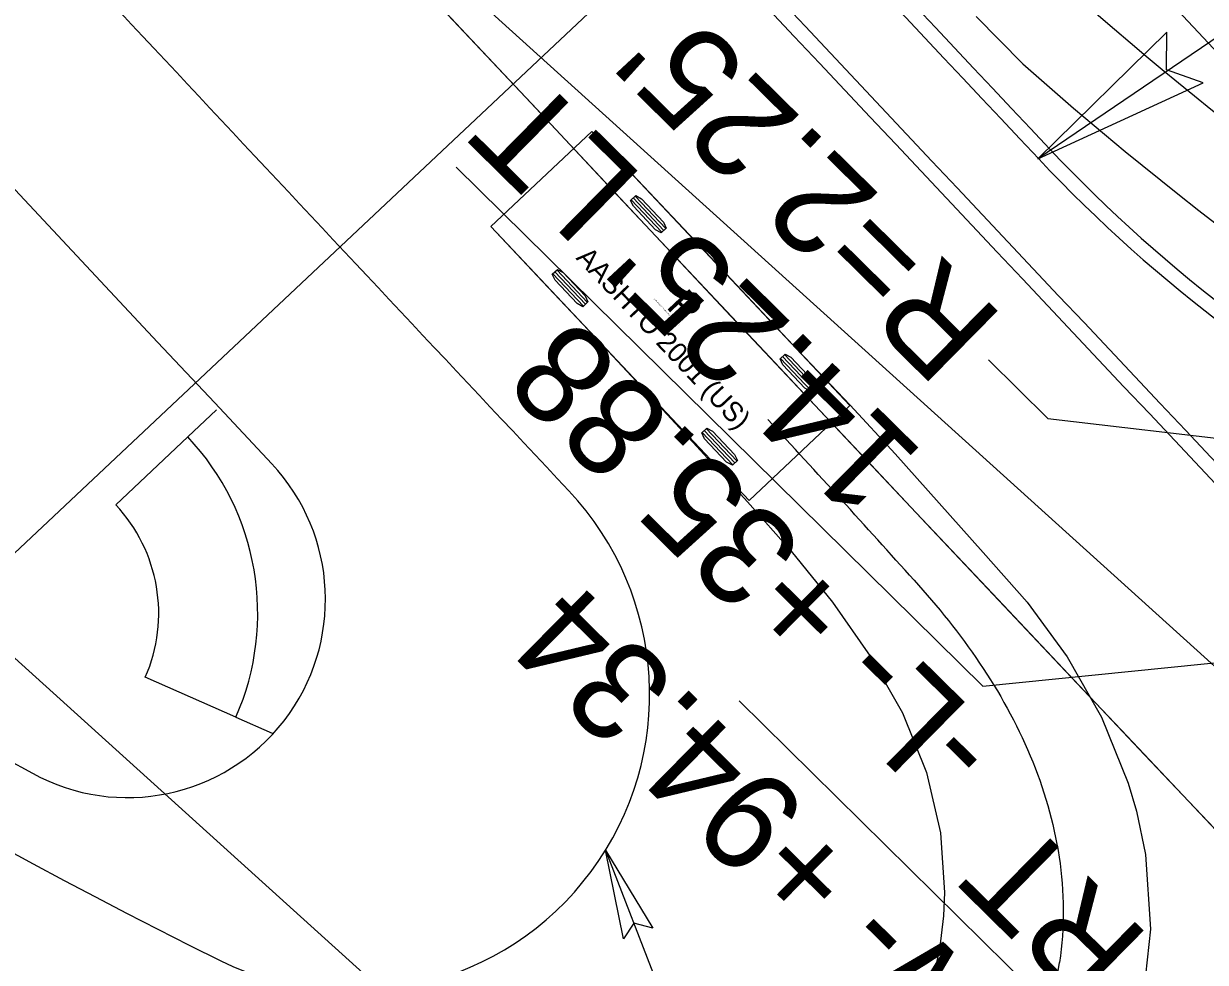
# Model space of a CAD drawing. Extents: x 1262642 to 1268358, y 767825 to 773481.
# Drawn here: x 1266689.1 to 1266748.8, y 772158.3 to 772205.7 of the extents above; entities that cross this region are included whole.
import ezdxf

# ---------------------------------------------------------------- set-up
doc = ezdxf.new("R2010")
doc.units = 0
for name, color, linetype in [('Prop Conc 2ft 6in Curb and Gutter', 7, 'Continuous'), ('Prop Conc 4in Sidewalk', 7, 'Continuous'), ('Prop Conc 5in Monolithic Keyed In Island', 7, 'Continuous'), ('Prop Dimension', 7, 'Continuous'), ('Prop Dimension Text', 7, 'Continuous'), ('Prop EOT', 7, 'Continuous'), ('Prop Horizontal Alignment', 7, 'Continuous'), ('Prop Horizontal Alignment Station Label', 7, 'Continuous'), ('Prop Lane Lines', 7, 'Continuous'), ('Prop Paved Shoulder', 7, 'Continuous'), ('Prop Shade Light', 7, 'Continuous'), ('Prop Shade Medium', 7, 'Continuous'), ('Prop Terminator CELL', 7, 'Continuous'), ('Scratch_Level_3', 7, 'Continuous')]:
    doc.layers.add(name, color=color, linetype=linetype)

msp = doc.modelspace()

# ---------------------------------------------------------------- linework, layer by layer
at = {"layer": 'Prop Conc 2ft 6in Curb and Gutter'}
for p, q in [((1266697.439, 772184.846), (1266698.896, 772186.216)), ((1266699.869, 772170.703), (1266701.7, 772169.897))]:
    msp.add_line(p, q, dxfattribs=at)
msp.add_arc((1266687.97, 772175.939), 13, 336.24997, 43.24771, dxfattribs=at)
at = {"layer": 'Prop Conc 4in Sidewalk'}
for p, q in [((1266693.797, 772181.42), (1266697.439, 772184.846)), ((1266699.869, 772170.703), (1266695.293, 772172.717))]:
    msp.add_line(p, q, dxfattribs=at)
msp.add_arc((1266687.97, 772175.939), 8, 336.24997, 43.24771, dxfattribs=at)
at = {"layer": 'Prop Conc 5in Monolithic Keyed In Island'}
for centre, radius, start, end in [((1275047.307, 780021.225), 11410.25, 222.8296601, 223.2792706), ((1275047.307, 780021.225), 11414.25, 222.8297896, 223.4298287), ((1266795.008, 772250.288), 75, 223.27927, 262.87792)]:
    msp.add_arc(centre, radius, start, end, dxfattribs=at)
at = {"layer": 'Prop Dimension'}
for p, q in [((1266731.744, 772134.821), (1266682.387, 772179.383)), ((1266718.539, 772163.987), (1266721.575, 772156.135))]:
    msp.add_line(p, q, dxfattribs=at)
at = {"layer": 'Prop Dimension Text'}
for p, q in [((1266710.996, 772198.463), (1266737.577, 772172.272)), ((1266737.867, 772188.735), (1266740.875, 772185.77)), ((1266751.861, 772145.344), (1266725.28, 772171.535))]:
    msp.add_line(p, q, dxfattribs=at)
for points in [[(1266754.434, 772208.43), (1266740.368, 772198.877)], [(1266740.875, 772185.77), (1266761.026, 772183.425)], [(1266737.577, 772172.272), (1266758.096, 772174.335)]]:
    msp.add_lwpolyline(points, dxfattribs=at)
at = {"layer": 'Prop EOT'}
for centre, radius, start, end in [((1275047.307, 780021.225), 11409.5, 222.8296601, 223.2792706), ((1275047.307, 780021.225), 11415, 222.8297896, 223.4298287), ((1266840.27, 772443.458), 318.091, 223.23333, 243.65317), ((1275047.307, 780021.225), 11439, 222.9935866, 223.2588472), ((1266795.008, 772250.288), 74.25, 223.27927, 262.87792), ((1266705.758, 772171.851), 15, 243.65317, 43.25885)]:
    msp.add_arc(centre, radius, start, end, dxfattribs=at)
at = {"layer": 'Prop Horizontal Alignment'}
msp.add_arc((1275047.307, 780021.225), 11400, 222.9935866, 225.4043192, dxfattribs=at)
at = {"layer": 'Prop Horizontal Alignment Station Label'}
for p, q in [((1266683.114, 772173.743), (1266860.999, 772340.982)), ((1266769.823, 772154.715), (1266566.881, 772338.064))]:
    msp.add_line(p, q, dxfattribs=at)
at = {"layer": 'Prop Lane Lines'}
for start, end in [(216.3674993, 223.5476842), (222.9935866, 225.3637298)]:
    msp.add_arc((1275047.307, 780021.225), 11427, start, end, dxfattribs=at)
at = {"layer": 'Prop Paved Shoulder'}
for centre, radius, start, end in [((1275047.307, 780021.225), 11449, 220.5050908, 223.2024475), ((1266840.27, 772443.458), 314.091, 223.23333, 241.33253), ((1266694.39, 772176.643), 10, 241.33253, 43.20245)]:
    msp.add_arc(centre, radius, start, end, dxfattribs=at)
at = {"layer": 'Prop Shade Light'}
for centre, radius, start, end in [((1275047.307, 780021.225), 11449, 220.5050908, 223.2024475), ((1266840.27, 772443.458), 314.091, 223.23333, 241.33253), ((1266840.27, 772443.458), 318.091, 223.23333, 243.65317), ((1275047.307, 780021.225), 11439, 222.9935866, 223.2588472), ((1266694.39, 772176.643), 10, 241.33253, 43.20245), ((1266705.758, 772171.851), 15, 243.65317, 43.25885)]:
    msp.add_arc(centre, radius, start, end, dxfattribs=at)
at = {"layer": 'Prop Shade Medium'}
for centre, radius, start, end in [((1275047.307, 780021.225), 11410.25, 222.8296601, 223.2792706), ((1275047.307, 780021.225), 11414.25, 222.8297896, 223.4298287), ((1266795.008, 772250.288), 75, 223.27927, 262.87792)]:
    msp.add_arc(centre, radius, start, end, dxfattribs=at)
at = {"layer": 'Prop Terminator CELL'}
for points in [[(1266746.884, 772205.276), (1266740.368, 772198.877), (1266748.719, 772202.715), (1266746.862, 772203.375)], [(1266719.439, 772159.51), (1266718.539, 772163.987), (1266720.917, 772160.055), (1266719.963, 772160.303)]]:
    msp.add_lwpolyline(points, close=True, dxfattribs=at)
at = {"layer": 'Scratch_Level_3'}
for p, q in [((1266717.837, 772200.259), (1266712.745, 772195.456)), ((1266730.874, 772186.437), (1266717.837, 772200.259)), ((1266721.369, 772195.171), (1266719.826, 772196.808)), ((1266721.472, 772195.267), (1266719.928, 772196.904)), ((1266721.574, 772195.364), (1266720.03, 772197)), ((1266712.745, 772195.456), (1266725.782, 772181.634)), ((1266717.414, 772191.44), (1266715.87, 772193.077)), ((1266717.516, 772191.536), (1266715.972, 772193.173)), ((1266717.618, 772191.633), (1266716.075, 772193.27)), ((1266728.917, 772187.169), (1266727.373, 772188.805)), ((1266729.019, 772187.265), (1266727.476, 772188.902)), ((1266729.122, 772187.362), (1266727.578, 772188.998)), ((1266725.782, 772181.634), (1266730.874, 772186.437)), ((1266730.874, 772186.437), (1266730.874, 772186.437)), ((1266725.166, 772183.631), (1266723.622, 772185.267)), ((1266724.961, 772183.438), (1266723.418, 772185.074)), ((1266725.064, 772183.534), (1266723.52, 772185.171))]:
    msp.add_line(p, q, dxfattribs=at)
for points in [[(1266737.254, 772206.068), (1266739.603, 772203.675), (1266742.157, 772201.436), (1266744.774, 772199.257), (1266747.424, 772197.118), (1266748.494, 772196.274)], [(1266717.837, 772200.259), (1266720.452, 772197.502), (1266723.058, 772194.736), (1266725.66, 772191.966), (1266728.267, 772189.202), (1266730.885, 772186.446), (1266730.885, 772186.446), (1266733.156, 772183.994), (1266735.375, 772181.501), (1266737.61, 772179.019), (1266739.82, 772176.501), (1266741.845, 772173.746), (1266743.58, 772170.701), (1266744.931, 772167.368), (1266745.341, 772165.96)], [(1266748.494, 772196.274), (1266750.108, 772195.021), (1266752.825, 772192.967), (1266755.573, 772190.956), (1266758.353, 772188.988), (1266761.164, 772187.064), (1266764.004, 772185.184), (1266766.874, 772183.349), (1266769.78, 772181.571), (1266772.846, 772180.001), (1266776.103, 772178.723), (1266779.535, 772177.787), (1266783.056, 772177.117), (1266786.607, 772176.625), (1266790.178, 772176.311), (1266793.761, 772176.178), (1266797.345, 772176.224), (1266800.923, 772176.45), (1266804.486, 772176.855), (1266808.023, 772177.439), (1266811.527, 772178.196), (1266814.996, 772179.071), (1266815.341, 772179.168)], [(1266712.745, 772195.456), (1266715.353, 772192.692), (1266717.958, 772189.925), (1266720.553, 772187.149), (1266723.137, 772184.363), (1266725.706, 772181.563), (1266725.706, 772181.563), (1266725.706, 772181.563), (1266727.901, 772179.075), (1266729.987, 772176.499), (1266731.892, 772173.789), (1266733.522, 772170.913), (1266734.739, 772167.917), (1266735.445, 772164.865), (1266735.648, 772161.854), (1266735.6, 772160.683)], [(1266734.117, 772177.61), (1266734.34, 772177.362), (1266734.561, 772177.113), (1266734.78, 772176.861), (1266734.997, 772176.608), (1266735.212, 772176.354), (1266735.425, 772176.097), (1266735.636, 772175.839), (1266735.845, 772175.579), (1266736.051, 772175.317), (1266736.255, 772175.054), (1266736.456, 772174.788), (1266736.655, 772174.52), (1266736.851, 772174.251), (1266737.045, 772173.98), (1266737.235, 772173.706), (1266737.423, 772173.431), (1266737.608, 772173.154), (1266737.79, 772172.874), (1266737.969, 772172.593), (1266738.145, 772172.31), (1266738.318, 772172.025), (1266738.487, 772171.738), (1266738.653, 772171.448), (1266738.815, 772171.157), (1266738.973, 772170.864), (1266739.129, 772170.569), (1266739.28, 772170.272), (1266739.427, 772169.973), (1266739.571, 772169.672), (1266739.71, 772169.369), (1266739.846, 772169.065), (1266739.977, 772168.758), (1266740.104, 772168.45), (1266740.226, 772168.14), (1266740.345, 772167.828), (1266740.458, 772167.515), (1266740.567, 772167.2), (1266740.671, 772166.883), (1266740.771, 772166.565), (1266740.865, 772166.246), (1266740.955, 772165.925), (1266741.04, 772165.602), (1266741.119, 772165.278), (1266741.193, 772164.953), (1266741.262, 772164.627), (1266741.325, 772164.3), (1266741.383, 772163.972), (1266741.436, 772163.643), (1266741.482, 772163.313), (1266741.523, 772162.982), (1266741.559, 772162.65), (1266741.588, 772162.318), (1266741.611, 772161.986), (1266741.629, 772161.653), (1266741.64, 772161.32), (1266741.645, 772160.986), (1266741.644, 772160.653), (1266741.636, 772160.32), (1266741.622, 772159.987), (1266741.602, 772159.654), (1266741.575, 772159.322), (1266741.542, 772158.99), (1266741.502, 772158.659), (1266741.455, 772158.329)], [(1266745.341, 772165.96), (1266745.793, 772163.779), (1266746.057, 772160.001), (1266745.624, 772156.142), (1266744.59, 772152.34), (1266743.062, 772148.708), (1266741.067, 772145.309), (1266740.146, 772144.028)], [(1266735.6, 772160.683), (1266735.4, 772158.977), (1266734.767, 772156.305), (1266733.824, 772153.889), (1266732.59, 772151.662), (1266731.073, 772149.619), (1266729.3, 772147.796), (1266728.525, 772147.136)]]:
    msp.add_lwpolyline(points, dxfattribs=at)
for points in [[(1266721.599, 772195.388), (1266721.344, 772195.147), (1266721.051, 772195.303), (1266719.939, 772196.482), (1266719.8, 772196.784), (1266720.056, 772197.024), (1266720.349, 772196.868), (1266721.46, 772195.689)], [(1266717.644, 772191.657), (1266717.389, 772191.416), (1266717.095, 772191.572), (1266715.984, 772192.751), (1266715.845, 772193.053), (1266716.1, 772193.294), (1266716.393, 772193.137), (1266717.505, 772191.958)], [(1266729.147, 772187.386), (1266728.892, 772187.145), (1266728.599, 772187.301), (1266727.487, 772188.48), (1266727.348, 772188.781), (1266727.603, 772189.022), (1266727.896, 772188.866), (1266729.008, 772187.687)], [(1266725.191, 772183.655), (1266724.936, 772183.414), (1266724.643, 772183.57), (1266723.532, 772184.749), (1266723.392, 772185.051), (1266723.648, 772185.291), (1266723.941, 772185.135), (1266725.052, 772183.956)]]:
    msp.add_lwpolyline(points, close=True, dxfattribs=at)
for centre, radius, start, end in [((1266882.309, 772367.05), 212.577, 228.35539, 237.4405), ((1266037.326, 771550.883), 937.179, 41.96975, 42.641124), ((1266716.484, 772162.028), 25.244, 283.88943, 351.57475)]:
    msp.add_arc(centre, radius, start, end, dxfattribs=at)

# ---------------------------------------------------------------- texts
at = {"layer": 'Prop Dimension'}
msp.add_text("R=2.25'", height=5, rotation=135.42387, dxfattribs=at).set_placement((1266738.726, 772190.825))
at = {"layer": 'Prop Dimension Text'}
for s, p in [("14.25' LT", (1266734.689, 772183.955)), ('-L- +35.88', (1266738.649, 772169.524)), ('-Y38SW- +94.34', (1266752.336, 772142.872)), ("2.32' RT", (1266757.6, 772148.215))]:
    msp.add_text(s, height=5, rotation=135.42387, dxfattribs=at).set_placement(p)
at = {"layer": 'Scratch_Level_3'}
for s, height, p in [('AASHTO 2001 (US)', 1, (1266717.002, 772193.85)), ('(c) 2016 Transoft Solutions, Inc. All rights reserved.', 0.06, (1266720.949, 772191.816)), ('P', 1.5, (1266721.554, 772191.393))]:
    msp.add_text(s, height=height, rotation=313.32573, dxfattribs=at).set_placement(p)

doc.saveas('drawing.dxf')
